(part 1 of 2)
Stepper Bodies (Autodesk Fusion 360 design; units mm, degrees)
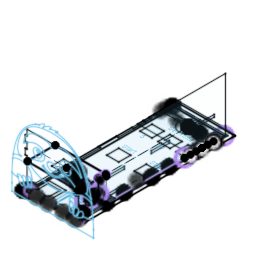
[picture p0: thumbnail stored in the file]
parameter "stepper_length" = 40
parameter "stepper_width" = 42.25
parameter "stepper_height" = 42.25 (= "stepper_width")
parameter "wall_thickness" = 2
parameter "stepper_screw_diameter" = 4
parameter "base_screw_diameter" = 5
parameter "base_thickness" = 2
parameter "base_flap_size" = 15
parameter "side_to_screw" = 6
parameter "stepper_circle_diameter" = 22
parameter "material_thickness" = 3
parameter "car_base_length" = 250
parameter "front_to_wheel" = 20
parameter "small_wheel_diameter" = 30
parameter "front_wheel_to_screw" = 2
parameter "finger_length" = 9.6 (= "10 mm - 2 * 0.2 mm")
parameter "motor_cap_thickness" = 1
parameter "motor_cap_bottom_height" = 3
parameter "motor_cap_top_height" = 1
parameter "cap_hole_width" = 30
parameter "cap_hole_height" = 20
parameter "car_height" = 90
parameter "base_to_layer_1" = 42.25 (= "material_thickness + stepper_height - motor_cap_bottom_height")
parameter "slit_length" = 30
parameter "green_to_middle" = -5
parameter "bottom_to_layer1" = 10
sketch "MotorHolderBase" plane through (0, 0, 0) normal (0, 0, 1) x axis (1, 0, 0)
  line L1 (80, 0) -> (0, 0)
  line L2 (80, 42.25) -> (80, 0)
  line L3 (0, 42.25) -> (80, 42.25)
  line L4 (0, 0) -> (0, 42.25)
  line L5 (-2, 0) -> (0, 0)
  line L6 (-2, -2) -> (-2, 0)
  line L7 (0, -2) -> (-2, -2)
  line L8 (0, 0) -> (0, -2)
  line L9 (82, -2) -> (-2, -2)
  line L10 (82, 44.25) -> (82, -2)
  line L11 (-2, 44.25) -> (82, 44.25)
  line L12 (-2, -2) -> (-2, 44.25)
  line L13 (82, 44.25) -> (-2, 44.25)
  line L14 (82, 59.25) -> (82, 44.25)
  line L15 (-2, 59.25) -> (82, 59.25)
  line L16 (-2, 44.25) -> (-2, 59.25)
  line L17 (82, 44.25) -> (-2, 44.25)
  line L18 (82, 51.75) -> (82, 44.25)
  line L19 (-2, 51.75) -> (82, 51.75)
  line L20 (-2, 44.25) -> (-2, 51.75)
  line L21 (-2, 51.75) -> (40, 51.75)
  line L22 (40, 44.25) -> (40, 59.25)
  circle C1 centre (40, 51.75) radius 2.5
  circle C2 centre (19, 51.75) radius 2.5
  circle C3 centre (61, 51.75) radius 2.5
  point P1 (0, 0)
  point P2 (0, 0)
  point P6 (0, 0)
  point P17 (82, 51.75)
  point P19 (40, 51.75)
  point P20 (40, 51.75)
  point P21 (19, 51.75)
  point P22 (40, 59.25)
  point P23 (40, 44.25)
  point P3 (80, 0)
  point P5 (0, 42.25)
  point P7 (-2, 0)
  point P9 (0, -2)
  point P8 (-2, -2)
  point P10 (82, -2)
  point P12 (-2, 44.25)
  point P13 (82, 44.25)
  point P15 (-2, 59.25)
  horizontal L1
  vertical L2
  horizontal L3
  vertical L4
  coincident P1 P2
  horizontal L5
  vertical L6
  horizontal L7
  vertical L8
  coincident P1 P6
  horizontal L9
  vertical L10
  horizontal L11
  vertical L12
  horizontal L13
  vertical L14
  horizontal L15
  vertical L16
  horizontal L17
  vertical L18
  horizontal L19
  vertical L20
  midpoint L14 P17
  midpoint L19 P19
  coincident P19 P20
  midpoint L21 P21
  midpoint L15 P22
  midpoint L17 P23
  symmetric C2 L22 C3
  dimension "d9" distance P2 P3 = 80 (= "2 * stepper_length")
  dimension "d10" distance P2 P5 = 42.25 (= "stepper_width")
  dimension "d11" distance P6 P7 = 2 (= "wall_thickness")
  dimension "d12" distance P6 P9 = 2 (= "wall_thickness")
  dimension "d13" distance P8 P10 = 84 (= "2 * stepper_length + 2 * wall_thickness")
  dimension "d14" distance P8 P12 = 46.25 (= "stepper_width + 2 * wall_thickness")
  dimension "d15" distance P12 P13 = 84 (= "stepper_length * 2 + 2 * wall_thickness")
  dimension "d16" distance P12 P15 = 15 (= "base_flap_size")
  dimension "d17" diameter C1 = 5 (= "base_screw_diameter")
  dimension "d18" diameter C2 = 5 (= "base_screw_diameter")
extrude "Extrude1" new body sketch "MotorHolderBase" profile of L1 L2 L3 L4 L9 L10 L11 L12 along normal blind 42.25 (= "stepper_height")
extrude "Extrude2" add sketch "MotorHolderBase" profile of L1 L2 L3 L4 L9 L10 L11 L12 L14 L15 L16 C1 C2 C3 no distance stored
sketch "MotorHolderSide" plane through (82, 0, 0) normal (1, 0, 0) x axis (0, 1, 0)
  line L1 (44.25, 42.25) -> (44.25, 0)
  line L2 (-2, 42.25) -> (44.25, 42.25)
  line L3 (-2, -2) -> (-2, 42.25)
  line L4 (59.25, -2) -> (-2, -2)
  line L5 (59.25, 0) -> (59.25, -2)
  line L6 (44.25, 0) -> (59.25, 0)
  line L7 (6, 0) -> (0, 0)
  line L8 (6, 6) -> (6, 0)
  line L9 (0, 6) -> (6, 6)
  line L10 (0, 0) -> (0, 6)
  line L11 (21.125, 0) -> (0, 0)
  line L12 (21.125, 21.125) -> (21.125, 0)
  line L13 (0, 21.125) -> (21.125, 21.125)
  line L14 (0, 0) -> (0, 21.125)
  line L15 (10.125, 42.25) -> (10.125, 21.125)
  line L16 (32.125, 42.25) -> (32.125, 21.125)
  circle C1 centre (6, 6) radius 2
  circle C2 centre (36.25, 6) radius 2
  circle C3 centre (6, 36.25) radius 2
  circle C4 centre (36.25, 36.25) radius 2
  circle C5 centre (21.125, 21.125) radius 11
  point P1 (0, 0)
  point P8 (0, 0)
  point P10 (6, 6)
  point P12 (6, 6)
  point P13 (0, 0)
  point P15 (21.125, 21.125)
  point P20 (21.125, 21.125)
  point P21 (10.125, 21.125)
  point P23 (32.125, 21.125)
  point P22 (10.125, 42.25)
  point P24 (32.125, 42.25)
  point P9 (6, 0)
  point P11 (0, 6)
  point P14 (21.125, 0)
  point P16 (0, 21.125)
  horizontal L7
  vertical L8
  horizontal L9
  vertical L10
  coincident P1 P8
  coincident P10 P12
  horizontal L11
  vertical L12
  horizontal L13
  vertical L14
  coincident P1 P13
  symmetric C1 L12 C2
  symmetric C1 L13 C3
  symmetric L13 C2 C4
  coincident P15 P20
  perpendicular L2 L15
  coincident L13 P21
  tangent C5 L15
  symmetric L12 P21 P23
  symmetric L12 P22 P24
  dimension "d24" distance P8 P9 = 6 (= "side_to_screw")
  dimension "d25" distance P8 P11 = 6 (= "side_to_screw")
  dimension "d26" diameter C1 = 4 (= "stepper_screw_diameter")
  dimension "d27" distance P13 P14 = 21.125 (= "stepper_width / 2")
  dimension "d28" distance P13 P16 = 21.125 (= "stepper_height / 2")
  dimension "d32" diameter C5 = 22 (= "stepper_circle_diameter")
  dimension "d33" distance P21 P22 = 21.125 (= "stepper_height / 2")
extrude "Extrude4" cut sketch "MotorHolderSide" profile of L2 C5 L15 L16 against normal blind 100
sketch "CarBase" plane through (0, 0, 0) normal (0, 0, 1) x axis (1, 0, 0)
  line L1 (-6, 0) -> (0, 0)
  line L2 (-6, -6) -> (-6, 0)
  line L3 (0, -6) -> (-6, -6)
  line L4 (0, 0) -> (0, -6)
  line L5 (-6, 244) -> (86, 244)
  line L6 (40, 244) -> (-6, 244)
  line L7 (40, 224) -> (40, 244)
  line L8 (-6, 224) -> (40, 224)
  line L9 (-6, 244) -> (-6, 224)
  line L10 (86, 224) -> (-6, 224)
  line L11 (57, 224) -> (55, 224)
  line L12 (57, 221.5) -> (57, 226.5)
  line L13 (-6, 234.4) -> (-6, 244)
  line L14 (-3, 224) -> (-6, 224)
  line L15 (-3, 214.4) -> (-3, 224)
  line L16 (-6, 214.4) -> (-3, 214.4)
  line L17 (-6, 224) -> (-6, 244)
  line L18 (-6, 204.8) -> (-6, 214.4)
  line L19 (-3, 204.8) -> (-6, 204.8)
  line L20 (-3, 195.2) -> (-3, 204.8)
  line L21 (-6, 195.2) -> (-3, 195.2)
  line L22 (-6, 204.8) -> (-6, 214.4)
  line L23 (-6, 185.6) -> (-6, 195.2)
  line L24 (-3, 185.6) -> (-6, 185.6)
  line L25 (-3, 176) -> (-3, 185.6)
  line L26 (-6, 176) -> (-3, 176)
  line L27 (-6, 185.6) -> (-6, 195.2)
  line L28 (-6, -6) -> (-6, 176)
  line L29 (3.6, -6) -> (-6, -6)
  line L30 (13.2, -3) -> (13.2, -6)
  line L31 (3.6, -3) -> (13.2, -3)
  line L32 (3.6, -6) -> (3.6, -3)
  line L33 (3.6, -6) -> (-6, -6)
  line L34 (22.8, -6) -> (13.2, -6)
  line L35 (32.4, -3) -> (32.4, -6)
  line L36 (22.8, -3) -> (32.4, -3)
  line L37 (22.8, -6) -> (22.8, -3)
  line L38 (22.8, -6) -> (13.2, -6)
  line L39 (40, -6) -> (40, 244)
  line L40 (76.4, -6) -> (76.4, -3)
  line L41 (76.4, -3) -> (66.8, -3)
  line L42 (66.8, -3) -> (66.8, -6)
  line L43 (57.2, -6) -> (57.2, -3)
  line L44 (57.2, -3) -> (47.6, -3)
  line L45 (47.6, -3) -> (47.6, -6)
  line L46 (47.6, -6) -> (32.4, -6)
  line L47 (66.8, -6) -> (57.2, -6)
  line L48 (86, -6) -> (76.4, -6)
  line L49 (83, 214.4) -> (83, 224)
  line L50 (86, 214.4) -> (83, 214.4)
  line L51 (83, 224) -> (86, 224)
  line L52 (83, 204.8) -> (86, 204.8)
  line L53 (83, 195.2) -> (83, 204.8)
  line L54 (86, 195.2) -> (83, 195.2)
  line L55 (83, 185.6) -> (86, 185.6)
  line L56 (83, 176) -> (83, 185.6)
  line L57 (86, 176) -> (83, 176)
  line L58 (86, 244) -> (86, 224)
  line L59 (86, 214.4) -> (86, 204.8)
  line L60 (86, 176) -> (86, -6)
  line L61 (86, 195.2) -> (86, 185.6)
  circle C1 centre (40, 224) radius 15
  circle C2 centre (19, 51.75) radius 2.5
  circle C3 centre (40, 51.75) radius 2.5
  circle C4 centre (61, 51.75) radius 2.5
  circle C5 centre (59.5, 224) radius 2.5
  circle C6 centre (20.5, 224) radius 2.5
  circle C7 centre (19, 51.75) radius 2.5
  circle C8 centre (40, 51.75) radius 2.5
  circle C9 centre (61, 51.75) radius 2.5
  point P1 (0, 0)
  point P2 (0, 0)
  point P10 (40, 224)
  point P12 (40, 224)
  point P18 (40, 224)
  point P19 (55, 224)
  point P21 (59.5, 224)
  point P20 (57, 224)
  point P48 (40, -6)
  point P40 (3.6, -6)
  point P50 (76.4, -6)
  point P41 (13.2, -6)
  point P52 (66.8, -6)
  point P42 (13.2, -3)
  point P51 (66.8, -3)
  point P43 (3.6, -3)
  point P49 (76.4, -3)
  point P44 (22.8, -6)
  point P54 (57.2, -6)
  point P45 (32.4, -6)
  point P56 (47.6, -6)
  point P46 (32.4, -3)
  point P55 (47.6, -3)
  point P47 (22.8, -3)
  point P53 (57.2, -3)
  point P11 (-6, 224)
  point P60 (86, 224)
  point P29 (-3, 224)
  point P57 (83, 224)
  point P30 (-3, 214.4)
  point P58 (83, 214.4)
  point P31 (-6, 214.4)
  point P59 (86, 214.4)
  point P32 (-6, 204.8)
  point P61 (86, 204.8)
  point P33 (-3, 204.8)
  point P62 (83, 204.8)
  point P34 (-3, 195.2)
  point P63 (83, 195.2)
  point P35 (-6, 195.2)
  point P64 (86, 195.2)
  point P36 (-6, 185.6)
  point P65 (86, 185.6)
  point P37 (-3, 185.6)
  point P66 (83, 185.6)
  point P38 (-3, 176)
  point P67 (83, 176)
  point P39 (-6, 176)
  point P68 (86, 176)
  point P3 (-6, 0)
  point P5 (0, -6)
  point P4 (-6, -6)
  point P6 (86, -6)
  point P8 (-6, 244)
  point P9 (40, 244)
  point P22 (57, 226.5)
  point P23 (57, 221.5)
  point P28 (-6, 234.4)
  horizontal L1
  vertical L2
  horizontal L3
  vertical L4
  coincident P1 P2
  horizontal L33
  vertical L60
  horizontal L5
  vertical L17
  horizontal L6
  vertical L7
  horizontal L8
  vertical L9
  coincident P10 P12
  midpoint L10 P18
  coincident P12 P18
  perpendicular L10 L58
  coincident C1 P19
  coincident L10 P19
  perpendicular L11 L58
  coincident L10 P21
  midpoint P20 L12
  perpendicular L11 L12
  tangent C5 L12
  symmetric L7 C5 C6
  concentric C2 C7
  concentric C3 C8
  concentric C4 C9
  perpendicular L8 L13
  horizontal L14
  vertical L15
  horizontal L16
  collinear L17 L22
  perpendicular L16 L18
  horizontal L19
  vertical L20
  horizontal L21
  collinear L22 L27
  perpendicular L21 L23
  horizontal L24
  vertical L25
  horizontal L26
  collinear L27 L28
  perpendicular L29 L60
  vertical L30
  horizontal L31
  vertical L32
  collinear L33 L38
  vertical L35
  horizontal L36
  vertical L37
  collinear L38 L46
  coincident P48 L46
  perpendicular L39 L46
  symmetric P40 L39 P50
  symmetric P41 L39 P52
  symmetric P42 L39 P51
  symmetric P43 L39 P49
  symmetric P44 L39 P54
  symmetric P45 L39 P56
  symmetric P46 L39 P55
  symmetric P47 L39 P53
  collinear L46 L47
  collinear L47 L48
  symmetric P11 L39 P60
  symmetric P29 L39 P57
  symmetric P30 L39 P58
  symmetric P31 L39 P59
  symmetric P32 L39 P61
  symmetric P33 L39 P62
  symmetric P34 L39 P63
  symmetric P35 L39 P64
  symmetric P36 L39 P65
  symmetric P37 L39 P66
  symmetric P38 L39 P67
  symmetric P39 L39 P68
  collinear L58 L59
  collinear L59 L61
  collinear L60 L61
  dimension "d40" distance P2 P3 = 6 (= "material_thickness + wall_thickness + motor_cap_thickness")
  dimension "d41" distance P2 P5 = 6 (= "material_thickness + wall_thickness + motor_cap_thickness")
  dimension "d44" distance P4 P6 = 92 (= "car_base_width")
  dimension "d45" distance P4 P8 = 250 (= "car_base_length")
  dimension "d47" distance P8 P9 = 46 (= "car_base_width / 2")
  dimension "d48" distance P8 P11 = 20 (= "front_to_wheel")
  dimension "d50" diameter C1 = 30 (= "small_wheel_diameter")
  dimension "d52" distance P19 P20 = 2 (= "front_wheel_to_screw")
  dimension "d53" diameter C5 = 5 (= "base_screw_diameter")
  dimension "d54" distance P22 P23 = 5
  dimension "d55" diameter C7 = 5 (= "base_screw_diameter")
  dimension "d56" diameter C8 = 5 (= "base_screw_diameter")
  dimension "d57" diameter C9 = 5 (= "base_screw_diameter")
  dimension "d60" distance P8 P28 = 9.6 (= "finger_length")
  dimension "d61" distance P11 P29 = 3 (= "material_thickness")
  dimension "d62" distance P11 P31 = 9.6 (= "finger_length")
  dimension "d63" distance P31 P32 = 9.6 (= "finger_length")
  dimension "d64" distance P32 P33 = 3 (= "material_thickness")
  dimension "d65" distance P32 P35 = 9.6 (= "finger_length")
  dimension "d92" distance P35 P36 = 9.6 (= "finger_length")
  dimension "d93" distance P36 P37 = 3 (= "material_thickness")
  dimension "d94" distance P36 P39 = 9.6 (= "finger_length")
  dimension "d95" distance P4 P40 = 9.6 (= "finger_length")
  dimension "d96" distance P40 P41 = 9.6 (= "finger_length")
  dimension "d97" distance P40 P43 = 3 (= "material_thickness")
  dimension "d98" distance P41 P44 = 9.6 (= "finger_length")
  dimension "d99" distance P44 P45 = 9.6 (= "finger_length")
  dimension "d100" distance P44 P47 = 3 (= "material_thickness")
  dimension "d157" distance L28 L60 = 92
  dimension "d158" distance L5 P50 = 250
work_plane "WorkPlane2" sketch "MotorHolderBase" AlongDistance 42.25 (= "stepper_height")
sketch "MotorHolderTop" plane through (0, 0, 42.25) normal (0, 0, 1) x axis (1, 0, 0)
  line L1 (82, 44.25) -> (-2, 44.25)
  line L2 (-2, -2) -> (-2, 44.25)
  line L3 (82, -2) -> (-2, -2)
  line L4 (82, 32.125) -> (82, 10.125)
  line L5 (82, 44.25) -> (82, -2)
  line L6 (82, 8) -> (82, 4)
  line L7 (-3, 44.25) -> (-2, 44.25)
  line L8 (-3, 45.25) -> (-3, 44.25)
  line L9 (-2, 45.25) -> (-3, 45.25)
  line L10 (-2, 44.25) -> (-2, 45.25)
  line L11 (-3, -2) -> (-2, -2)
  line L12 (-3, -3) -> (-3, -2)
  line L13 (-2, -3) -> (-3, -3)
  line L14 (-2, -2) -> (-2, -3)
  line L15 (83, -2) -> (82, -2)
  line L16 (83, -3) -> (83, -2)
  line L17 (82, -3) -> (83, -3)
  line L18 (82, -2) -> (82, -3)
  line L19 (83, 44.25) -> (82, 44.25)
  line L20 (83, 45.25) -> (83, 44.25)
  line L21 (82, 45.25) -> (83, 45.25)
  line L22 (82, 44.25) -> (82, 45.25)
  line L23 (83, 45.25) -> (-3, 45.25)
  line L24 (83, -3) -> (83, 45.25)
  line L25 (-3, -3) -> (83, -3)
  line L26 (-3, 45.25) -> (-3, -3)
  line L27 (82, 44.25) -> (-2, 44.25)
  line L28 (82, -2) -> (82, 44.25)
  line L29 (-2, -2) -> (82, -2)
  line L30 (-2, 44.25) -> (-2, -2)
  line L31 (82, 21.125) -> (-2, 21.125)
  line L32 (40, -2) -> (40, 44.25)
  line L33 (25, 31.125) -> (55, 31.125)
  line L34 (25, 11.125) -> (25, 31.125)
  line L35 (55, 11.125) -> (25, 11.125)
  line L36 (55, 31.125) -> (55, 11.125)
  line L37 (25, 11.125) -> (55, 31.125)
  line L38 (55, 11.125) -> (25, 31.125)
  point P2 (-2, 44.25)
  point P13 (-2, 44.25)
  point P4 (-2, -2)
  point P17 (-2, -2)
  point P5 (82, -2)
  point P21 (82, -2)
  point P8 (82, 44.25)
  point P25 (82, 44.25)
  point P33 (-2, 21.125)
  point P34 (82, 21.125)
  point P35 (40, 44.25)
  point P36 (40, -2)
  point P41 (40, 21.125)
  point P14 (-3, 44.25)
  point P16 (-2, 45.25)
  point P18 (-3, -2)
  point P20 (-2, -3)
  point P22 (83, -2)
  point P24 (82, -3)
  point P26 (83, 44.25)
  point P28 (82, 45.25)
  point P39 (25, 11.125)
  point P40 (55, 11.125)
  point P38 (25, 31.125)
  horizontal L7
  vertical L8
  horizontal L9
  vertical L10
  coincident P2 P13
  horizontal L11
  vertical L12
  horizontal L13
  vertical L14
  coincident P4 P17
  horizontal L15
  vertical L16
  horizontal L17
  vertical L18
  coincident P5 P21
  horizontal L19
  vertical L20
  horizontal L21
  vertical L22
  coincident P8 P25
  horizontal L23
  vertical L24
  horizontal L25
  vertical L26
  horizontal L27
  vertical L28
  horizontal L29
  vertical L30
  midpoint L2 P33
  midpoint L5 P34
  midpoint L1 P35
  midpoint L29 P36
  horizontal L33
  perpendicular L33 L34
  parallel L33 L35
  parallel L34 L36
  coincident L37 P41
  coincident L38 P41
  midpoint L32 P41
  dimension "d68" distance P13 P14 = 1 (= "motor_cap_thickness")
  dimension "d69" distance P13 P16 = 1 (= "motor_cap_thickness")
  dimension "d70" distance P17 P18 = 1 (= "motor_cap_thickness")
  dimension "d71" distance P17 P20 = 1 (= "motor_cap_thickness")
  dimension "d72" distance P21 P22 = 1 (= "motor_cap_thickness")
  dimension "d73" distance P21 P24 = 1 (= "motor_cap_thickness")
  dimension "d74" distance P25 P26 = 1 (= "motor_cap_thickness")
  dimension "d75" distance P25 P28 = 1 (= "motor_cap_thickness")
  dimension "d86" distance P39 P40 = 30 (= "cap_hole_width")
  dimension "d87" distance P38 P39 = 20 (= "cap_hole_height")
extrude "Extrude6" add sketch "MotorHolderTop" profile of L1 L2 L3 L4 L5 L6 L23 L24 L25 L26 L27 L28 L29 L30 no distance stored
extrude "Extrude7" new body sketch "MotorHolderTop" profile of L1 L2 L3 L4 L5 L6 L23 L24 L25 L26 L27 L28 L29 L30 no distance stored
extrude "Extrude10" add sketch "MotorHolderTop" profile of L1 L2 L3 L4 L5 L6 L23 L24 L25 L26 L27 L28 L29 L30 L33 L34 L35 L36 along normal blind 1 (= "motor_cap_top_height")
sketch "CarSide" plane through (82, 0, 0) normal (1, 0, 0) x axis (0, 1, 0)
  line L1 (32.125, 39.25) -> (44.25, 39.25)
  line L2 (32.125, 21.125) -> (32.125, 39.25)
  line L3 (10.125, 39.25) -> (10.125, 21.125)
  line L4 (-2, 39.25) -> (10.125, 39.25)
  line L5 (-2, -2) -> (-2, 39.25)
  line L6 (59.25, -2) -> (-2, -2)
  line L7 (59.25, 0) -> (59.25, -2)
  line L8 (44.25, 0) -> (59.25, 0)
  line L9 (44.25, 39.25) -> (44.25, 0)
  line L10 (176, 0) -> (-6, 0)
  line L11 (-6, -2) -> (-6, 0)
  line L12 (244, 88) -> (244, -2)
  line L13 (-6, 88) -> (244, 88)
  line L14 (-3, 39.25) -> (45.25, 39.25)
  line L15 (-6, 39.25) -> (-3, 39.25)
  line L16 (176, -2) -> (176, 0)
  line L17 (185.6, -2) -> (185.6, 0)
  line L18 (195.2, -2) -> (195.2, 0)
  line L19 (204.8, -2) -> (204.8, 0)
  line L20 (214.4, -2) -> (214.4, 0)
  line L21 (224, -2) -> (224, 0)
  line L22 (185.6, -5) -> (185.6, -2)
  line L23 (176, -5) -> (185.6, -5)
  line L24 (176, -2) -> (176, -5)
  line L25 (176, -2) -> (-6, -2)
  line L26 (204.8, -5) -> (204.8, -2)
  line L27 (195.2, -5) -> (204.8, -5)
  line L28 (195.2, -2) -> (195.2, -5)
  line L29 (195.2, -2) -> (185.6, -2)
  line L30 (224, -5) -> (224, -2)
  line L31 (214.4, -5) -> (224, -5)
  line L32 (214.4, -2) -> (214.4, -5)
  line L33 (214.4, -2) -> (204.8, -2)
  line L34 (244, -2) -> (224, -2)
  line L35 (-6, 78.4) -> (-6, 88)
  line L36 (-3, 78.4) -> (-6, 78.4)
  line L37 (-3, 68.8) -> (-3, 78.4)
  line L38 (-6, 68.8) -> (-3, 68.8)
  line L39 (-6, 78.4) -> (-6, 88)
  line L40 (-6, 59.2) -> (-6, 68.8)
  line L41 (-3, 59.2) -> (-6, 59.2)
  line L42 (-3, 49.6) -> (-3, 59.2)
  line L43 (-6, 49.6) -> (-3, 49.6)
  line L44 (-6, 59.2) -> (-6, 68.8)
  line L45 (-6, -2) -> (-6, 49.6)
  line L46 (45.25, 34.25) -> (45.25, 39.25)
  line L47 (75.25, 34.25) -> (45.25, 34.25)
  line L48 (75.25, 38.25) -> (75.25, 34.25)
  line L49 (45.25, 38.25) -> (75.25, 38.25)
  line L50 (45.25, 34.25) -> (45.25, 38.25)
  line L51 (120.25, 38.25) -> (150.25, 38.25)
  line L52 (120.25, 34.25) -> (120.25, 38.25)
  line L53 (150.25, 34.25) -> (120.25, 34.25)
  line L54 (150.25, 38.25) -> (150.25, 34.25)
  line L55 (195.25, 38.25) -> (225.25, 38.25)
  line L56 (195.25, 34.25) -> (195.25, 38.25)
  line L57 (225.25, 34.25) -> (195.25, 34.25)
  line L58 (225.25, 38.25) -> (225.25, 34.25)
  line L59 (45.25, -2) -> (45.25, 39.25)
  line L60 (45.25, 8) -> (45.25, -2)
  line L61 (95.25, 8) -> (45.25, 8)
  line L62 (45.25, 12.25) -> (75.25, 12.25)
  line L63 (45.25, 8.25) -> (45.25, 12.25)
  line L64 (75.25, 8.25) -> (45.25, 8.25)
  line L65 (75.25, 12.25) -> (75.25, 8.25)
  line L66 (120.25, 8.25) -> (120.25, 12.25)
  line L67 (120.25, 12.25) -> (150.25, 12.25)
  line L68 (150.25, 8.25) -> (120.25, 8.25)
  line L69 (150.25, 12.25) -> (150.25, 8.25)
  line L70 (195.25, 8.25) -> (195.25, 12.25)
  line L71 (195.25, 12.25) -> (225.25, 12.25)
  line L72 (225.25, 8.25) -> (195.25, 8.25)
  line L73 (225.25, 12.25) -> (225.25, 8.25)
  arc A1 centre (21.125, 21.125) radius 11 clockwise from (32.125, 21.125) to (10.125, 21.125)
  arc A2 centre (21.125, 21.125) radius 11 clockwise from (32.125, 21.125) to (10.125, 21.125)
  circle C1 centre (21.125, 21.125) radius 11
  point P13 (-6, 0)
  point P15 (-6, 0)
  point P21 (-3, 39.25)
  point P22 (-3, 39.25)
  point P23 (-6, 39.25)
  point P20 (45.25, 39.25)
  point P24 (45.25, 39.25)
  point P14 (176, 0)
  point P35 (176, 0)
  point P30 (185.6, 0)
  point P37 (185.6, 0)
  point P31 (195.2, 0)
  point P39 (195.2, 0)
  point P32 (204.8, 0)
  point P41 (204.8, 0)
  point P34 (214.4, 0)
  point P43 (214.4, 0)
  point P33 (224, 0)
  point P45 (224, 0)
  point P76 (45.25, -2)
  point P77 (45.25, 8)
  point P16 (-6, -2)
  point P17 (244, -2)
  point P19 (-6, 88)
  point P36 (176, -2)
  point P47 (185.6, -2)
  point P49 (176, -5)
  point P40 (195.2, -2)
  point P50 (204.8, -2)
  point P52 (195.2, -5)
  point P44 (214.4, -2)
  point P53 (224, -2)
  point P55 (214.4, -5)
  point P56 (-6, 78.4)
  point P57 (-3, 78.4)
  point P59 (-6, 68.8)
  point P60 (-6, 59.2)
  point P61 (-3, 59.2)
  point P63 (-6, 49.6)
  point P64 (45.25, 34.25)
  point P65 (75.25, 34.25)
  point P67 (45.25, 38.25)
  point P78 (95.25, 8)
  coincident P13 P15
  perpendicular L10 L11
  horizontal L25
  vertical L12
  horizontal L13
  vertical L39
  coincident P21 P22
  coincident P23 L45
  perpendicular L15 L45
  coincident P20 P24
  concentric A2 C1
  coincident P14 P35
  perpendicular L16 L25
  coincident P30 P37
  perpendicular L17 L29
  coincident P31 P39
  perpendicular L18 L29
  coincident P32 P41
  perpendicular L19 L33
  coincident P34 P43
  perpendicular L20 L33
  coincident P33 P45
  perpendicular L21 L34
  vertical L22
  horizontal L23
  vertical L24
  collinear L25 L29
  vertical L26
  horizontal L27
  vertical L28
  collinear L29 L33
  vertical L30
  horizontal L31
  vertical L32
  collinear L33 L34
  perpendicular L13 L35
  horizontal L36
  vertical L37
  horizontal L38
  collinear L39 L44
  horizontal L41
  vertical L42
  horizontal L43
  collinear L44 L45
  perpendicular L14 L46
  horizontal L47
  vertical L48
  horizontal L49
  vertical L50
  vertical L59
  coincident L6 P76
  coincident L59 P77
  perpendicular L60 L61
  dimension "d103" distance P15 P16 = 2 (= "base_thickness")
  dimension "d104" distance P16 P17 = 250 (= "car_base_length")
  dimension "d105" distance P16 P19 = 90 (= "car_height")
  dimension "d113" diameter C1 = 22 (= "stepper_circle_diameter")
  dimension "d114" distance P36 P47 = 9.6 (= "finger_length")
  dimension "d115" distance P36 P49 = 3 (= "material_thickness")
  dimension "d116" distance P40 P50 = 9.6 (= "finger_length")
  dimension "d117" distance P40 P52 = 3 (= "material_thickness")
  dimension "d118" distance P44 P53 = 9.6 (= "finger_length")
  dimension "d119" distance P44 P55 = 3 (= "material_thickness")
  dimension "d120" distance P19 P56 = 9.6 (= "finger_length")
  dimension "d121" distance P56 P57 = 3 (= "material_thickness")
  dimension "d122" distance P56 P59 = 9.6 (= "finger_length")
  dimension "d123" distance P59 P60 = 9.6 (= "finger_length")
  dimension "d124" distance P60 P61 = 3 (= "material_thickness")
  dimension "d125" distance P60 P63 = 9.6 (= "finger_length")
  dimension "d150" distance P24 P64 = -5 (= "green_to_middle")
  dimension "d151" distance P64 P65 = 30 (= "slit_length")
  dimension "d152" distance P64 P67 = 4 (= "material_thickness + 1 mm")
  dimension "d172" distance P76 P77 = 10 (= "bottom_to_layer1")
  dimension "d173" distance P77 P78 = 50
  dimension "d155" R-Pattern1-uDistance = 150
  dimension "d156" R-Pattern1-vDistance = 0
  dimension "d176" R-Pattern2-uDistance = 0
  dimension "d177" R-Pattern2-vDistance = -26
sketch "CarBack" plane through (0, -2, 0) normal (0, -1, 0) x axis (1, 0, 0)
  line L1 (-2, 39.25) -> (82, 39.25)
  line L2 (-2, -2) -> (-2, 39.25)
  line L3 (82, -2) -> (-2, -2)
  line L4 (82, 39.25) -> (82, -2)
  line L5 (3.6, 0) -> (-6, 0)
  line L6 (22.8, 0) -> (13.2, 0)
  line L7 (47.6, 0) -> (32.4, 0)
  line L8 (66.8, 0) -> (57.2, 0)
  line L9 (-3, 0) -> (-6, 0)
  line L10 (83, 0) -> (86, 0)
  line L11 (83, -2) -> (82, -2)
  line L12 (83, -10.8119) -> (83, 0)
  line L13 (-10, 88) -> (82, 88)
  line L14 (83, 88) -> (-3, 88)
  line L15 (86, 0) -> (76.4, 0)
  line L16 (3.6, -2) -> (3.6, 0)
  line L17 (13.2, -2) -> (13.2, 0)
  line L18 (22.8, -2) -> (22.8, 0)
  line L19 (32.4, -2) -> (32.4, 0)
  line L20 (47.6, -2) -> (47.6, 0)
  line L21 (57.2, -2) -> (57.2, 0)
  line L22 (66.8, -2) -> (66.8, 0)
  line L23 (76.4, -2) -> (76.4, 0)
  line L24 (13.2, -5) -> (13.2, -2)
  line L25 (3.6, -5) -> (13.2, -5)
  line L26 (3.6, -2) -> (3.6, -5)
  line L27 (-3, -2) -> (3.6, -2)
  line L28 (32.4, -5) -> (32.4, -2)
  line L29 (22.8, -5) -> (32.4, -5)
  line L30 (22.8, -2) -> (22.8, -5)
  line L31 (13.2, -2) -> (22.8, -2)
  line L32 (57.2, -5) -> (57.2, -2)
  line L33 (47.6, -5) -> (57.2, -5)
  line L34 (47.6, -2) -> (47.6, -5)
  line L35 (32.4, -2) -> (47.6, -2)
  line L36 (76.4, -5) -> (76.4, -2)
  line L37 (66.8, -5) -> (76.4, -5)
  line L38 (66.8, -2) -> (66.8, -5)
  line L39 (76.4, -2) -> (83, -2)
  line L40 (57.2, -2) -> (66.8, -2)
  line L41 (82, 68.8) -> (82, 78.4)
  line L42 (82, 49.6) -> (82, 59.2)
  line L43 (83, 78.4) -> (82, 78.4)
  line L44 (83, 68.8) -> (82, 68.8)
  line L45 (83, 59.2) -> (82, 59.2)
  line L46 (83, 49.6) -> (82, 49.6)
  line L47 (86, 78.4) -> (83, 78.4)
  line L48 (86, 68.8) -> (86, 78.4)
  line L49 (83, 68.8) -> (86, 68.8)
  line L50 (83, 78.4) -> (83, 88)
  line L51 (86, 59.2) -> (83, 59.2)
  line L52 (86, 49.6) -> (86, 59.2)
  line L53 (83, 49.6) -> (86, 49.6)
  line L54 (83, 59.2) -> (83, 68.8)
  line L55 (83, -2) -> (83, 49.6)
  line L56 (40, -19.3098) -> (40, 88)
  line L57 (-6, 78.4) -> (-3, 78.4)
  line L58 (-6, 68.8) -> (-6, 78.4)
  line L59 (-3, 68.8) -> (-6, 68.8)
  line L60 (-6, 59.2) -> (-3, 59.2)
  line L61 (-6, 49.6) -> (-6, 59.2)
  line L62 (-3, 49.6) -> (-6, 49.6)
  line L63 (-3, 88) -> (-3, 78.4)
  line L64 (-3, 49.6) -> (-3, -2)
  line L65 (-3, 68.8) -> (-3, 59.2)
  point P6 (-6, 0)
  point P14 (-6, 0)
  point P16 (86, 0)
  point P17 (86, 0)
  point P19 (82, -2)
  point P20 (82, -2)
  point P21 (83, -2)
  point P23 (82, 88)
  point P24 (82, 88)
  point P27 (-3, 88)
  point P15 (-3, 0)
  point P7 (3.6, 0)
  point P31 (3.6, 0)
  point P8 (13.2, 0)
  point P33 (13.2, 0)
  point P9 (22.8, 0)
  point P35 (22.8, 0)
  point P10 (32.4, 0)
  point P37 (32.4, 0)
  point P11 (47.6, 0)
  point P39 (47.6, 0)
  point P12 (57.2, 0)
  point P41 (57.2, 0)
  point P13 (66.8, 0)
  point P43 (66.8, 0)
  point P29 (76.4, 0)
  point P45 (76.4, 0)
  point P59 (82, 78.4)
  point P63 (82, 78.4)
  point P60 (82, 68.8)
  point P65 (82, 68.8)
  point P61 (82, 59.2)
  point P67 (82, 59.2)
  point P62 (82, 49.6)
  point P69 (82, 49.6)
  point P77 (40, 88)
  point P64 (83, 78.4)
  point P79 (-3, 78.4)
  point P68 (83, 59.2)
  point P83 (-3, 59.2)
  point P71 (86, 78.4)
  point P80 (-6, 78.4)
  point P72 (86, 68.8)
  point P81 (-6, 68.8)
  point P73 (83, 68.8)
  point P82 (-3, 68.8)
  point P74 (86, 59.2)
  point P84 (-6, 59.2)
  point P75 (86, 49.6)
  point P85 (-6, 49.6)
  point P76 (83, 49.6)
  point P86 (-3, 49.6)
  point P18 (83, 0)
  point P25 (-10, 88)
  point P32 (3.6, -2)
  point P47 (13.2, -2)
  point P49 (3.6, -5)
  point P36 (22.8, -2)
  point P50 (32.4, -2)
  point P52 (22.8, -5)
  point P40 (47.6, -2)
  point P53 (57.2, -2)
  point P55 (47.6, -5)
  point P44 (66.8, -2)
  point P56 (76.4, -2)
  point P58 (66.8, -5)
  coincident P6 P14
  perpendicular L2 L9
  coincident P16 P17
  perpendicular L4 L10
  coincident P19 P20
  perpendicular L4 L11
  perpendicular L11 L12
  coincident P21 L12
  coincident P23 P24
  horizontal L13
  horizontal L39
  vertical L64
  horizontal L14
  vertical L50
  coincident L13 P27
  coincident P15 L64
  coincident P7 P31
  perpendicular L16 L27
  coincident P8 P33
  perpendicular L3 L17
  coincident P9 P35
  perpendicular L18 L31
  coincident P10 P37
  perpendicular L19 L35
  coincident P11 P39
  perpendicular L20 L35
  coincident P12 P41
  perpendicular L21 L40
  coincident P13 P43
  perpendicular L22 L40
  coincident P29 P45
  perpendicular L23 L39
  vertical L24
  horizontal L25
  vertical L26
  collinear L27 L31
  vertical L28
  horizontal L29
  vertical L30
  collinear L31 L35
  vertical L32
  horizontal L33
  vertical L34
  collinear L35 L40
  vertical L36
  horizontal L37
  vertical L38
  collinear L39 L40
  coincident P59 P63
  perpendicular L43 L50
  coincident P60 P65
  perpendicular L44 L54
  coincident P61 P67
  perpendicular L45 L54
  coincident P62 P69
  perpendicular L46 L55
  horizontal L47
  vertical L48
  horizontal L49
  collinear L50 L54
  horizontal L51
  vertical L52
  horizontal L53
  collinear L54 L55
  midpoint L14 P77
  perpendicular L35 L56
  symmetric P64 L56 P79
  symmetric P68 L56 P83
  symmetric P71 L56 P80
  symmetric P72 L56 P81
  symmetric P73 L56 P82
  symmetric P74 L56 P84
  symmetric P75 L56 P85
  symmetric P76 L56 P86
  collinear L63 L65
  collinear L64 L65
  dimension "d126" distance P14 P15 = 3 (= "material_thickness")
  dimension "d127" distance P17 P18 = 3 (= "material_thickness")
  dimension "d128" distance P24 P25 = 92 (= "car_base_width")
  dimension "d129" distance P32 P47 = 9.6 (= "finger_length")
  dimension "d130" distance P32 P49 = 3 (= "material_thickness")
  dimension "d131" distance P36 P50 = 9.6 (= "finger_length")
  dimension "d132" distance P36 P52 = 3 (= "material_thickness")
  dimension "d133" distance P40 P53 = 9.6 (= "finger_length")
  dimension "d134" distance P40 P55 = 3 (= "material_thickness")
  dimension "d135" distance P44 P56 = 9.6 (= "finger_length")
  dimension "d136" distance P44 P58 = 3 (= "material_thickness")
  dimension "d137" distance P64 P71 = 3 (= "material_thickness")
  dimension "d138" distance P64 P73 = 9.6 (= "finger_length")
  dimension "d139" distance P68 P74 = 3 (= "material_thickness")
  dimension "d140" distance P68 P76 = 9.6 (= "finger_length")
sketch "Sloth" plane through (0, 0, 0) normal (0, 1, 0) x axis (1, 0, 0)
  curve K1 (12.4109, -28.5567) -> (10.29, -31.2409)
  curve K2 (15.9809, -30.5824) -> (12.4109, -28.5567)
  curve K3 (16.24, -30.827) -> (15.9809, -30.5824)
  curve K4 (16.5719, -31.1284) -> (16.24, -30.827)
  curve K5 (16.7213, -31.2573) -> (16.5719, -31.1284)
  line L1 (16.773, -31.3012) -> (16.7213, -31.2573)
  curve K6 (16.8973, -31.408) -> (16.773, -31.3012)
  curve K7 (17.1771, -31.6376) -> (16.8973, -31.408)
  line L2 (17.2167, -31.6696) -> (17.1771, -31.6376)
  curve K8 (17.5304, -31.9155) -> (17.2167, -31.6696)
  curve K9 (17.531, -31.9162) -> (17.5304, -31.9155)
  curve K10 (18.3146, -32.4937) -> (17.531, -31.9162)
  line L3 (18.3641, -32.5306) -> (18.3146, -32.4937)
  curve K11 (19.231, -33.1274) -> (18.3641, -32.5306)
  curve K12 (19.7764, -33.4814) -> (19.231, -33.1274)
  curve K13 (20.1772, -33.7393) -> (19.7764, -33.4814)
  line L4 (20.2453, -33.784) -> (20.1772, -33.7393)
  curve K14 (22.0744, -35.132) -> (20.2453, -33.784)
  curve K15 (22.5996, -35.6733) -> (22.0744, -35.132)
  curve K16 (22.6036, -35.6783) -> (22.5996, -35.6733)
  curve K17 (22.708, -35.8131) -> (22.6036, -35.6783)
  curve K18 (22.8348, -36.0018) -> (22.708, -35.8131)
  curve K19 (22.9696, -36.2418) -> (22.8348, -36.0018)
  curve K20 (23.4499, -36.9562) -> (22.9696, -36.2418)
  curve K21 (24.5639, -38.0957) -> (23.4499, -36.9562)
  curve K22 (24.5756, -38.1086) -> (24.5639, -38.0957)
  curve K23 (25.6692, -39.1925) -> (24.5756, -38.1086)
  curve K24 (25.6425, -39.3453) -> (25.6692, -39.1925)
  curve K25 (25.626, -39.4356) -> (25.6425, -39.3453)
  curve K26 (25.5713, -39.6927) -> (25.626, -39.4356)
  curve K27 (25.5628, -39.7319) -> (25.5713, -39.6927)
  curve K28 (25.5626, -39.733) -> (25.5628, -39.7319)
  line L5 (25.538, -39.8435) -> (25.5626, -39.733)
  curve K29 (25.4916, -40.0131) -> (25.538, -39.8435)
  line L6 (25.4787, -40.0588) -> (25.4916, -40.0131)
  curve K30 (25.4288, -40.2342) -> (25.4787, -40.0588)
  curve K31 (25.3659, -40.4244) -> (25.4288, -40.2342)
  curve K32 (25.2961, -40.6185) -> (25.3659, -40.4244)
  curve K33 (25.2283, -40.791) -> (25.2961, -40.6185)
  curve K34 (25.1375, -40.9979) -> (25.2283, -40.791)
  line L7 (25.119, -41.038) -> (25.1375, -40.9979)
  curve K35 (25.066, -41.1511) -> (25.119, -41.038)
  curve K36 (24.9439, -41.3811) -> (25.066, -41.1511)
  line L8 (24.9204, -41.4243) -> (24.9439, -41.3811)
  curve K37 (24.8775, -41.5018) -> (24.9204, -41.4243)
  curve K38 (24.6617, -41.8413) -> (24.8775, -41.5018)
  line L9 (23.9134, -42.7367) -> (24.0681, -42.5699)
  curve K39 (23.4923, -43.1848) -> (23.9134, -42.7367)
  curve K40 (23.4754, -43.2075) -> (23.4923, -43.1848)
  line L10 (22.8589, -42.7667) -> (23.4754, -43.2075)
  curve K41 (22.45, -42.4789) -> (22.8589, -42.7667)
  line L11 (22.183, -42.291) -> (22.45, -42.4789)
  curve K42 (21.8421, -42.0515) -> (22.183, -42.291)
  curve K43 (21.3196, -41.6976) -> (21.8421, -42.0515)
  line L12 (21.0848, -41.539) -> (21.3196, -41.6976)
  curve K44 (20.8228, -41.3624) -> (21.0848, -41.539)
  curve K45 (19.7833, -40.7029) -> (20.8228, -41.3624)
  curve K46 (19.7655, -40.6934) -> (19.7833, -40.7029)
  curve K47 (18.3145, -40.0552) -> (19.7655, -40.6934)
  curve K48 (17.9172, -36.58) -> (18.7797, -37.2446)
  curve K49 (16.825, -37.3975) -> (17.9172, -36.58)
  curve K50 (16.7335, -37.5149) -> (16.825, -37.3975)
  curve K51 (15.5169, -38.6854) -> (16.7335, -37.5149)
  curve K52 (16.4488, -37.3526) -> (15.5592, -38.4934)
  curve K53 (16.7437, -37.1555) -> (16.4488, -37.3526)
  curve K54 (17.391, -35.946) -> (16.7437, -37.1555)
  curve K55 (16.4038, -35.5132) -> (16.8686, -35.5505)
  curve K56 (14.3145, -36.2374) -> (16.4038, -35.5132)
  curve K57 (14.0598, -36.3998) -> (14.3145, -36.2374)
  curve K58 (12.5979, -37.6437) -> (14.0598, -36.3998)
  curve K59 (11.8728, -37.2819) -> (12.5979, -37.6437)
  curve K60 (9.4983, -35.047) -> (11.8728, -37.2819)
  curve K61 (10.029, -31.89) -> (9.4983, -35.047)
  curve K62 (23.7298, -23.8377) -> (19.9343, -28.4931)
  curve K63 (24.5165, -22.9405) -> (23.7298, -23.8377)
  curve K64 (26.1486, -20.7284) -> (24.5165, -22.9405)
  curve K65 (25.2234, -26.8031) -> (26.1486, -20.7284)
  curve K66 (25.574, -33.4337) -> (25.2234, -26.8031)
  line L13 (23.7662, -34.5089) -> (23.8356, -34.4608)
  curve K67 (22.7523, -35.3097) -> (23.7662, -34.5089)
  curve K68 (22.3139, -34.873) -> (22.7523, -35.3097)
  curve K69 (20.4389, -33.489) -> (22.3139, -34.873)
  line L14 (20.3708, -33.4444) -> (20.4389, -33.489)
  curve K70 (19.9659, -33.1838) -> (20.3708, -33.4444)
  curve K71 (19.4281, -32.8349) -> (19.9659, -33.1838)
  curve K72 (18.5704, -32.2444) -> (19.4281, -32.8349)
  line L15 (18.5203, -32.2071) -> (18.5704, -32.2444)
  curve K73 (18.5198, -32.2067) -> (18.5203, -32.2071)
  curve K74 (17.8676, -31.7295) -> (18.5198, -32.2067)
  curve K75 (19.9343, -28.4931) -> (17.8676, -31.7295)
  curve K76 (24.8253, -37.8595) -> (24.8279, -37.8622)
  curve K77 (23.7031, -36.7106) -> (24.8253, -37.8595)
  curve K78 (23.2788, -36.072) -> (23.7031, -36.7106)
  curve K79 (23.1386, -35.8225) -> (23.2788, -36.072)
  curve K80 (22.9927, -35.6044) -> (23.1386, -35.8225)
  curve K81 (22.9776, -35.5841) -> (22.9927, -35.6044)
  curve K82 (23.0481, -35.5196) -> (22.9776, -35.5841)
  curve K83 (23.1462, -35.4332) -> (23.0481, -35.5196)
  curve K84 (23.2999, -35.3041) -> (23.1462, -35.4332)
  curve K85 (23.3985, -35.2233) -> (23.2999, -35.3041)
  curve K86 (23.5823, -35.0808) -> (23.3985, -35.2233)
  curve K87 (23.6721, -35.0121) -> (23.5823, -35.0808)
  curve K88 (23.9677, -34.7986) -> (23.6721, -35.0121)
  line L16 (24.0359, -34.751) -> (23.9677, -34.7986)
  curve K89 (24.4052, -34.502) -> (24.0359, -34.751)
  curve K90 (24.9388, -34.1745) -> (24.4052, -34.502)
  curve K91 (25.0319, -34.1201) -> (24.9388, -34.1745)
  curve K92 (25.6067, -33.8128) -> (25.5636, -33.8342)
  curve K93 (25.6498, -34.3465) -> (25.6067, -33.8128)
  curve K94 (25.71, -35.0951) -> (25.6498, -34.3465)
  line L17 (25.7516, -35.6735) -> (25.7442, -35.5578)
  curve K95 (25.7745, -36.0348) -> (25.7516, -35.6735)
  line L18 (25.781, -36.1658) -> (25.7745, -36.0348)
  curve K96 (25.7972, -36.5244) -> (25.781, -36.1658)
  line L19 (25.8013, -36.6523) -> (25.7972, -36.5244)
  curve K97 (25.8094, -37.025) -> (25.8013, -36.6523)
  line L20 (25.8106, -37.1376) -> (25.8094, -37.025)
  curve K98 (25.8086, -37.5429) -> (25.8106, -37.1376)
  line L21 (25.8074, -37.6211) -> (25.8086, -37.5429)
  curve K99 (25.7944, -37.9762) -> (25.8074, -37.6211)
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sketch "CarTop" plane through (0, 0, 0) normal (0, 0, 1) x axis (1, 0, 0)
  line L1 (92, 0) -> (0, 0)
  line L2 (92, 250) -> (92, 0)
  line L3 (0, 250) -> (92, 250)
  line L4 (0, 0) -> (0, 250)
  point P1 (0, 0)
  point P2 (0, 0)
  point P3 (92, 0)
  point P5 (0, 250)
  horizontal L1
  vertical L2
  horizontal L3
  vertical L4
  coincident P1 P2
  dimension "d159" distance P2 P3 = 92 (= "car_base_width")
  dimension "d160" distance P2 P5 = 250 (= "car_base_length")
sketch "CarMiddle" plane through (0, 0, 0) normal (0, 0, 1) x axis (1, 0, 0)
  line L1 (-3, -6) -> (-6, -6)
  line L2 (-3, -3) -> (-3, -6)
  line L3 (-6, -3) -> (-3, -3)
  line L4 (-6, -6) -> (-6, -3)
  line L5 (83, -3) -> (-3, -3)
  line L6 (-3, 241) -> (83, 241)
  line L7 (82, 45.25) -> (82, 75.25)
  line L8 (82, 120.25) -> (82, 150.25)
  line L9 (82, 195.25) -> (82, 225.25)
  line L10 (83, 225.25) -> (82, 225.25)
  line L11 (83, 195.25) -> (82, 195.25)
  line L12 (83, 150.25) -> (82, 150.25)
  line L13 (83, 120.25) -> (82, 120.25)
  line L14 (83, 75.25) -> (82, 75.25)
  line L15 (83, 45.25) -> (82, 45.25)
  line L16 (86, 225.25) -> (83, 225.25)
  line L17 (86, 195.25) -> (86, 225.25)
  line L18 (83, 195.25) -> (86, 195.25)
  line L19 (83, 241) -> (83, 225.25)
  line L20 (86, 150.25) -> (83, 150.25)
  line L21 (86, 120.25) -> (86, 150.25)
  line L22 (83, 120.25) -> (86, 120.25)
  line L23 (83, 195.25) -> (83, 150.25)
  line L24 (86, 75.25) -> (83, 75.25)
  line L25 (86, 45.25) -> (86, 75.25)
  line L26 (83, 45.25) -> (86, 45.25)
  line L27 (83, 45.25) -> (83, -3)
  line L28 (83, 120.25) -> (83, 75.25)
  line L29 (40, -3) -> (40, 241)
  line L30 (-6, 225.25) -> (-3, 225.25)
  line L31 (-6, 195.25) -> (-6, 225.25)
  line L32 (-3, 195.25) -> (-6, 195.25)
  line L33 (-6, 150.25) -> (-3, 150.25)
  line L34 (-6, 120.25) -> (-6, 150.25)
  line L35 (-3, 120.25) -> (-6, 120.25)
  line L36 (-6, 75.25) -> (-3, 75.25)
  line L37 (-6, 45.25) -> (-6, 75.25)
  line L38 (-3, 45.25) -> (-6, 45.25)
  line L39 (-3, -3) -> (-3, 45.25)
  line L40 (-3, 75.25) -> (-3, 120.25)
  line L41 (-3, 225.25) -> (-3, 241)
  line L42 (-3, 150.25) -> (-3, 195.25)
  line L43 (83, 45.25) -> (-3, 45.25)
  point P2 (-6, -6)
  point P6 (-6, -6)
  point P14 (82, 225.25)
  point P16 (82, 225.25)
  point P15 (82, 195.25)
  point P18 (82, 195.25)
  point P12 (82, 150.25)
  point P20 (82, 150.25)
  point P13 (82, 120.25)
  point P22 (82, 120.25)
  point P10 (82, 75.25)
  point P24 (82, 75.25)
  point P11 (82, 45.25)
  point P26 (82, 45.25)
  point P37 (40, 241)
  point P38 (40, -3)
  point P17 (83, 225.25)
  point P39 (-3, 225.25)
  point P21 (83, 150.25)
  point P43 (-3, 150.25)
  point P25 (83, 75.25)
  point P47 (-3, 75.25)
  point P28 (86, 225.25)
  point P40 (-6, 225.25)
  point P29 (86, 195.25)
  point P41 (-6, 195.25)
  point P30 (83, 195.25)
  point P42 (-3, 195.25)
  point P31 (86, 150.25)
  point P44 (-6, 150.25)
  point P32 (86, 120.25)
  point P45 (-6, 120.25)
  point P33 (83, 120.25)
  point P46 (-3, 120.25)
  point P34 (86, 75.25)
  point P48 (-6, 75.25)
  point P35 (86, 45.25)
  point P49 (-6, 45.25)
  point P36 (83, 45.25)
  point P50 (-3, 45.25)
  point P3 (-3, -6)
  point P5 (-6, -3)
  point P4 (-3, -3)
  point P7 (83, -3)
  point P9 (-3, 241)
  horizontal L1
  vertical L2
  horizontal L3
  vertical L4
  coincident P2 P6
  horizontal L5
  vertical L27
  horizontal L6
  vertical L41
  coincident P14 P16
  perpendicular L10 L19
  coincident P15 P18
  perpendicular L11 L23
  coincident P12 P20
  perpendicular L12 L23
  coincident P13 P22
  perpendicular L13 L28
  coincident P10 P24
  perpendicular L14 L28
  coincident P11 P26
  perpendicular L15 L27
  horizontal L16
  vertical L17
  horizontal L18
  collinear L19 L23
  horizontal L20
  vertical L21
  horizontal L22
  collinear L23 L28
  horizontal L24
  vertical L25
  horizontal L26
  collinear L27 L28
  midpoint L6 P37
  midpoint L5 P38
  symmetric P17 L29 P39
  symmetric P21 L29 P43
  symmetric P25 L29 P47
  symmetric P28 L29 P40
  symmetric P29 L29 P41
  symmetric P30 L29 P42
  symmetric P31 L29 P44
  symmetric P32 L29 P45
  symmetric P33 L29 P46
  symmetric P34 L29 P48
  symmetric P35 L29 P49
  symmetric P36 L29 P50
  collinear L39 L40
  collinear L40 L42
  collinear L41 L42
  dimension "d161" distance P2 P3 = 3 (= "material_thickness")
  dimension "d162" distance P2 P5 = 3 (= "material_thickness")
  dimension "d163" distance P4 P7 = 86 (= "car_base_width - 2 * material_thickness")
  dimension "d164" distance P4 P9 = 244 (= "car_base_length - 2 * material_thickness")
  dimension "d165" distance P17 P28 = 3 (= "material_thickness")
  dimension "d166" distance P17 P30 = 30 (= "slit_length")
  dimension "d167" distance P21 P31 = 3 (= "material_thickness")
  dimension "d168" distance P21 P33 = 30 (= "slit_length")
  dimension "d169" distance P25 P34 = 3 (= "material_thickness")
  dimension "d170" distance P25 P36 = 30 (= "slit_length")
canvas "Canvas1" sketch "CarBack"
sketch "CarFront" plane through (0, -2, 0) normal (0, -1, 0) x axis (1, 0, 0)
  curve K1 (11.5207, 102.5123) -> (-27.9756, -1.9134)
  curve K2 (17.2057, 104.3075) -> (11.5207, 102.5123)
  curve K3 (24.3182, 104.3075) -> (17.2057, 104.3075)
  curve K4 (35.3926, 107.4016) -> (24.3182, 104.3075)
  curve K5 (45.2389, 107.4016) -> (35.3926, 107.4016)
  curve K6 (107.9563, -1.8646) -> (45.2389, 107.4016)
  curve K7 (37.6347, 82.198) -> (-8.1687, 65.7627)
  curve K8 (87.4838, 63.2666) -> (37.6347, 82.198)
  curve K9 (52.2132, 58.228) -> (87.4838, 63.2666)
  curve K10 (80.8814, 40.8533) -> (52.2132, 58.228)
  curve K11 (-0.9287, 42.3876) -> (80.8814, 40.8533)
  curve K12 (-8.1687, 65.7627) -> (-0.9287, 42.3876)
  curve K13 (32.444, 58.228) -> (32.444, 58.228)
  curve K14 (54.2727, 47.8721) -> (23.1789, 47.8721)
  curve K15 (24.4927, 49.2954) -> (23.1789, 47.8721)
  curve K16 (53.5063, 49.2954) -> (24.4927, 49.2954)
  curve K17 (54.2727, 47.8721) -> (53.5063, 49.2954)
  curve K18 (96.0174, 44.3162) -> (-12.7305, 44.3162)
  curve K19 (-25.878, 40.5355) -> (-12.7305, 44.3162)
  curve K20 (103.7004, 40.5355) -> (96.0174, 44.3162)
  curve K21 (5.3942, 19.4595) -> (-26.6665, 34.2697)
  curve K22 (-18.1679, 11.6918) -> (-27.9857, 13.5038)
  curve K23 (-8.7996, 10.1383) -> (-18.1679, 11.6918)
  curve K24 (-18.1679, 11.6918) -> (-8.7996, 10.1383)
  curve K25 (-8.7831, 8.8003) -> (-11.1079, 14.3813)
  curve K26 (-2.3995, 16.2606) -> (-2.3995, 16.2606)
  curve K27 (-2.142, 15.509) -> (-3.5337, 14.9441)
  curve K28 (5.3942, 19.4595) -> (4.0489, 17.4843)
  curve K29 (104.6631, 34.4745) -> (69.0236, 19.4595)
  curve K30 (107.0513, 12.771) -> (90.167, 8.4789)
  curve K31 (69.0236, 19.4595) -> (69.0236, 19.4595)
  curve K32 (77.4281, 2.7343) -> (74.2096, 5.7958)
  curve K33 (77.4281, 2.7343) -> (74.2096, 5.7958)
  curve K34 (80.8822, 5.7958) -> (80.8822, 5.7958)
  curve K35 (82.584, 9.5138) -> (81.9131, 9.5138)
  line L1 (107.9585, -13.9134) -> (107.9585, -1.9134)
  line L2 (-27.9756, -13.9134) -> (107.9585, -13.9134)
  line L3 (-27.9756, -1.9134) -> (-27.9756, -13.9134)
  curve K36 (108.7679, -19.5445) -> (107.1447, 15.8153)
  circle C1 centre (14.4224, 62.4648) radius 6.8834
  circle C2 centre (63.0792, 61.444) radius 6.6176
  circle C3 centre (15.025, 65.1905) radius 1.8349
  circle C4 centre (63.5276, 64.5858) radius 1.8453
  point P73 (103.7004, 40.5355)
  point P74 (-26.6665, 34.2697)
  point P78 (-27.9857, 13.5038)
  point P86 (-11.1079, 14.3813)
  point P91 (-8.7831, 8.8003)
  point P99 (-3.5337, 14.9441)
  point P100 (-2.142, 15.509)
  point P106 (104.6631, 34.4745)
  point P109 (107.0513, 12.771)
  point P116 (74.638, 10.8737)
  point P128 (81.9131, 9.5138)
  point P129 (82.584, 9.5138)
  point P18 (107.9563, -1.8646)
  point P130 (107.9585, -1.9134)
  point P2 (-27.9756, -1.9134)
  point P132 (-27.9756, -13.9134)
  coincident K6 P73
  coincident K1 P74
  coincident K1 P78
  coincident K24 P86
  coincident K23 P91
  coincident K25 P99
  coincident K26 P100
  coincident K6 P106
  coincident K6 P109
  coincident K31 P116
  coincident K32 P128
  coincident K34 P129
  vertical L1
  horizontal L2
  vertical L3
  midpoint P18 K36
  coincident P130 K36
  dimension "d212" distance P2 P132 = 12
sketch "CarTopButtons" plane through (0, 0, 0) normal (0, 0, 1) x axis (1, 0, 0)
  line L1 (0, 250) -> (92, 250)
  line L2 (0, 0) -> (0, 250)
  line L3 (92, 250) -> (92, 0)
  line L4 (92, 0) -> (0, 0)
  line L5 (92, 0) -> (0, 0)
  line L6 (92, 250) -> (92, 0)
  line L7 (0, 250) -> (92, 250)
  line L8 (0, 0) -> (0, 250)
  line L9 (46, 0) -> (0, 0)
  line L10 (46, 125) -> (46, 0)
  line L11 (0, 125) -> (46, 125)
  line L12 (0, 0) -> (0, 125)
  line L13 (46, 250) -> (46, 125)
  line L14 (36, 177.5) -> (56, 177.5)
  line L15 (36, 197.5) -> (36, 177.5)
  line L16 (56, 197.5) -> (36, 197.5)
  line L17 (56, 177.5) -> (56, 197.5)
  line L18 (36, 197.5) -> (56, 177.5)
  line L19 (56, 197.5) -> (36, 177.5)
  line L20 (26, 177.5) -> (36, 177.5)
  line L21 (26, 197.5) -> (26, 177.5)
  line L22 (36, 197.5) -> (26, 197.5)
  line L23 (36, 177.5) -> (36, 197.5)
  line L24 (6, 177.5) -> (26, 177.5)
  line L25 (6, 197.5) -> (6, 177.5)
  line L26 (26, 197.5) -> (6, 197.5)
  line L27 (26, 177.5) -> (26, 197.5)
  line L28 (66, 197.5) -> (86, 197.5)
  line L29 (86, 197.5) -> (86, 177.5)
  line L30 (86, 177.5) -> (66, 177.5)
  line L31 (66, 197.5) -> (66, 177.5)
  curve K1
  curve K2
  curve K3
  curve K4
  curve K5
  curve K6
  curve K7
  curve K8
  curve K9
  curve K10
  curve K11
  curve K12
  curve K13
  curve K14
  curve K15
  curve K16
  line L32 (92, 172.6313) -> (0, 172.6313)
  curve K17
  curve K18
  curve K19
  curve K20
  line L33 (23, 125) -> (46, 125)
  line L34 (13, 135) -> (33, 135)
  line L35 (13, 115) -> (13, 135)
  line L36 (33, 115) -> (13, 115)
  line L37 (33, 135) -> (33, 115)
  line L38 (13, 115) -> (33, 135)
  line L39 (33, 115) -> (13, 135)
  line L40 (79, 135) -> (59, 135)
  line L41 (79, 115) -> (79, 135)
  line L42 (59, 115) -> (79, 115)
  line L43 (59, 135) -> (59, 115)
  curve K21
  curve K22
  curve K23
  curve K24
  line L44 (92, 144.2674) -> (0.2437, 144.2674)
  point P2 (92, 250)
  point P8 (92, 250)
  point P1 (0, 0)
  point P6 (0, 0)
  point P13 (46, 250)
  point P18 (46, 187.5)
  point P19 (26, 177.5)
  point P28 (66, 177.5)
  point P20 (26, 197.5)
  point P29 (66, 197.5)
  point P22 (6, 177.5)
  point P27 (86, 177.5)
  point P23 (6, 197.5)
  point P25 (86, 197.5)
  point P24 (26, 197.5)
  point P26 (66, 197.5)
  point P30 (0, 172.6313)
  point P31 (92, 172.6313)
  point P32 (23, 125)
  point P37 (23, 125)
  point P33 (33, 135)
  point P38 (59, 135)
  point P34 (13, 135)
  point P39 (79, 135)
  point P35 (13, 115)
  point P40 (79, 115)
  point P36 (33, 115)
  point P41 (59, 115)
  point P43 (92, 144.2674)
  point P10 (46, 0)
  point P12 (0, 125)
  point P16 (36, 197.5)
  point P17 (56, 197.5)
  point P15 (36, 177.5)
  point P21 (36, 197.5)
  horizontal L5
  vertical L6
  horizontal L7
  vertical L8
  coincident P2 P8
  coincident P1 P6
  horizontal L9
  vertical L10
  horizontal L11
  vertical L12
  midpoint L7 P13
  horizontal L14
  perpendicular L14 L15
  parallel L14 L16
  parallel L15 L17
  coincident L18 P18
  coincident L19 P18
  midpoint L13 P18
  horizontal L20
  vertical L21
  horizontal L22
  vertical L23
  horizontal L24
  vertical L25
  horizontal L26
  vertical L27
  symmetric L13 P19 P28
  symmetric L13 P20 P29
  symmetric L13 P22 P27
  symmetric L13 P23 P25
  symmetric L13 P24 P26
  midpoint L24
  coincident L8 P30
  coincident L3 P31
  perpendicular L3 L32
  midpoint L11 P32
  horizontal L34
  perpendicular L34 L35
  parallel L34 L36
  parallel L35 L37
  coincident L38 P37
  coincident L39 P37
  coincident P32 P37
  symmetric L13 P33 P38
  symmetric L13 P34 P39
  symmetric L13 P35 P40
  symmetric L13 P36 P41
  coincident L3 P43
  perpendicular L3 L44
  dimension "d178" distance P6 P10 = 46 (= "car_base_width / 2")
  dimension "d179" distance P6 P12 = 125 (= "car_base_length / 2")
  dimension "d180" distance P16 P17 = 20
  dimension "d181" distance P15 P16 = 20
  dimension "d182" distance P15 P19 = 10
  dimension "d183" distance P15 P21 = 20
  dimension "d184" distance P19 P22 = 20
  dimension "d185" distance P19 P24 = 20
  dimension "d196" distance P35 P36 = 20
  dimension "d197" distance P34 P35 = 20
  dimension "d186" Text1-Height = 10
  dimension "d188" Text2-Height = 10
  dimension "d189" Text2-Text = "'5'"
  dimension "d190" Text3-Height = 10
  dimension "d191" 10 = "'10'"
  dimension "d192" Text4-Height = 10
  dimension "d193" 20 = "'20'"
  dimension "d194" Text5-Height = 10
  dimension "d198" Text6-Height = 10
